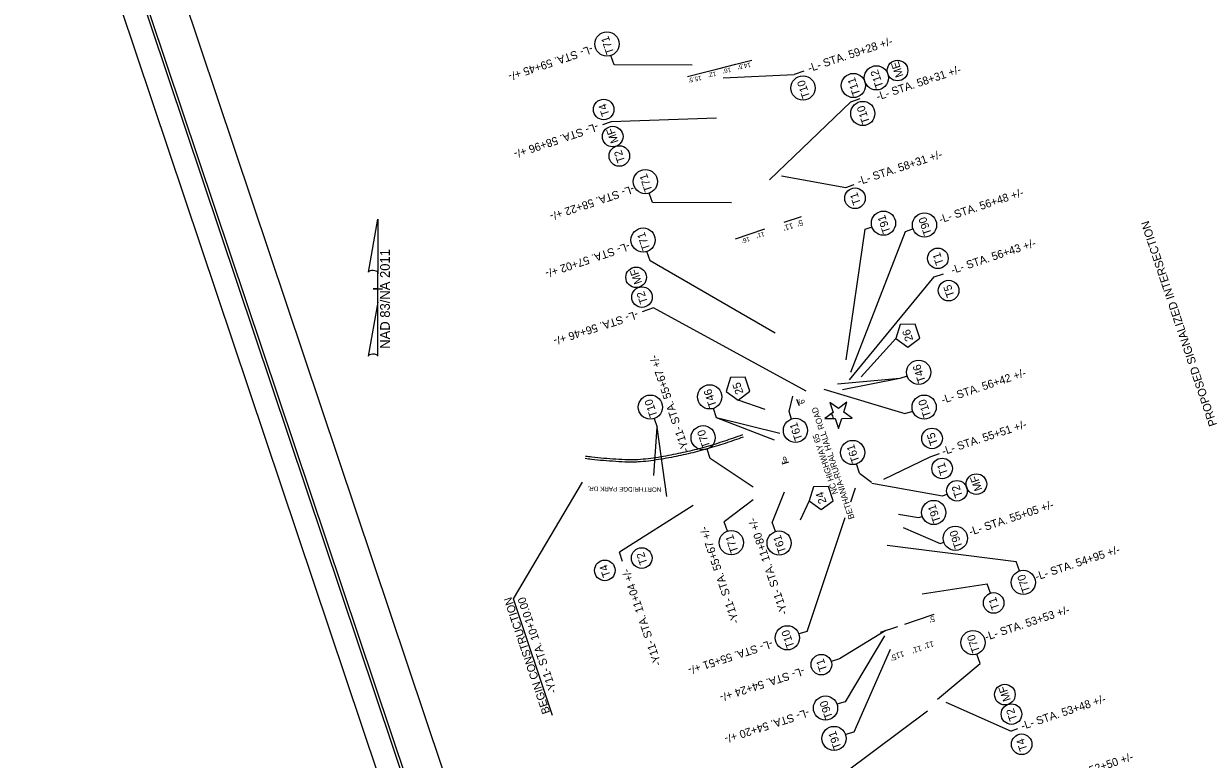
# Model space of a CAD drawing. Extents: x 1615436 to 1617119, y 903110 to 905145.
# Drawn here: x 1615436 to 1616462, y 903795 to 904439 of the extents above; entities that cross this region are included whole.
import ezdxf

# ---------------------------------------------------------------- set-up
doc = ezdxf.new("R2010")
doc.units = 0
for name, color, linetype in [('Default', 7, 'Continuous'), ('Prop Conc 2ft 6in Curb and Gutter', 7, 'Continuous'), ('Prop EOT', 7, 'Continuous'), ('Prop Horizontal Alignment Curve and Spiral Data', 7, 'Continuous'), ('Prop Horizontal Alignment Station Label', 7, 'Continuous'), ('Prop North Arrow NAD83 for Plan Sheets CELL', 7, 'Continuous'), ('Sheet Layout Plan Border', 7, 'Continuous'), ('Sheet Plan CELL', 7, 'Continuous'), ('Sheet Plot Border Inside CELL', 7, 'Continuous'), ('Sheet Plot Border Outside CELL', 7, 'Continuous'), ('Text', 7, 'Continuous')]:
    doc.layers.add(name, color=color, linetype=linetype)

msp = doc.modelspace()

# ---------------------------------------------------------------- linework, layer by layer
at = {"layer": 'Default'}
for p, q in [((1616143.4, 904097.7), (1616138.1, 904093.8)), ((1616138.1, 904093.8), (1616138.3, 904093.3)), ((1616138.3, 904093.3), (1616138.1, 904093.8)), ((1616138.3, 904093.3), (1616145.1, 904093.4))]:
    msp.add_line(p, q, dxfattribs=at)
for points in [[(1616144.9, 904098.8), (1616137.5, 904093.3), (1616146.7, 904093.4), (1616149.6, 904084.7), (1616152.4, 904093.5), (1616161.6, 904093.6), (1616154.1, 904098.9), (1616156.8, 904107.7), (1616149.5, 904102.2), (1616142, 904107.5), (1616144.9, 904098.8)], [(1616145.1, 904093.4), (1616146.7, 904093.4), (1616149.6, 904084.7), (1616152.4, 904093.5), (1616161.6, 904093.6), (1616154.1, 904098.9), (1616156.8, 904107.7), (1616149.5, 904102.2), (1616142, 904107.5), (1616144.9, 904098.8), (1616143.4, 904097.7)], [(1616138.1, 904093.8), (1616137.5, 904093.3), (1616138.3, 904093.3)]]:
    msp.add_lwpolyline(points, dxfattribs=at)
msp.add_ellipse((1616138.3, 904093.1), major_axis=(-0.95, 6.77), ratio=0.999591, start_param=4.623228, end_param=5.312334, dxfattribs=at)
msp.add_ellipse((1616138.3, 904093.1), major_axis=(-0.95, 6.77), ratio=0.999591, start_param=4.623228, end_param=5.312334, dxfattribs=at)
at = {"layer": 'Prop Conc 2ft 6in Curb and Gutter'}
msp.add_spline([(1616065.5, 904079.1), (1616049.8, 904073.6), (1616033.8, 904068.7), (1616025.7, 904066.4), (1616017.5, 904064.5), (1616009.2, 904062.7), (1616000.8, 904061), (1615991.9, 904059.4), (1615983, 904058.2), (1615974.1, 904057.4), (1615969.6, 904057.3), (1615965.2, 904057.3), (1615954.7, 904057.8), (1615944.1, 904058.5), (1615933.6, 904059.6), (1615928.3, 904060.2)], degree=3, dxfattribs=at)
at = {"layer": 'Prop EOT'}
msp.add_spline([(1616066.2, 904077.2), (1616050.4, 904071.7), (1616034.4, 904066.8), (1616026.2, 904064.5), (1616017.9, 904062.5), (1616009.6, 904060.7), (1616001.2, 904059), (1615992.2, 904057.5), (1615983.2, 904056.2), (1615974.2, 904055.4), (1615969.7, 904055.3), (1615965.2, 904055.3), (1615954.6, 904055.8), (1615944, 904056.6), (1615933.4, 904057.6), (1615928, 904058.3)], degree=3, dxfattribs=at)
at = {"layer": 'Prop Horizontal Alignment Curve and Spiral Data'}
msp.add_line((1615865.1, 903935.7), (1615925.7, 904037.8), dxfattribs=at)
at = {"layer": 'Prop Horizontal Alignment Station Label'}
msp.add_line((1615899.3, 903833.6), (1615865.1, 903935.7), dxfattribs=at)
at = {"layer": 'Prop North Arrow NAD83 for Plan Sheets CELL'}
for p, q in [((1615738.2, 904221.4), (1615746.4, 904267.8)), ((1615746.4, 904267.8), (1615746.4, 904267.8)), ((1615746.4, 904267.8), (1615746.4, 904267.8)), ((1615746.4, 904267.8), (1615746.4, 904220)), ((1615746.4, 904195.2), (1615746.4, 904221.4)), ((1615746.4, 904220), (1615746.4, 904221.3)), ((1615746, 904206.8), (1615742.4, 904206.8)), ((1615742.4, 904206.8), (1615742.4, 904206.8)), ((1615742.5, 904206.8), (1615750.5, 904206.8)), ((1615746.4, 904195.2), (1615738.1, 904147.9)), ((1615746.5, 904148.1), (1615746.4, 904195.2))]:
    msp.add_line(p, q, dxfattribs=at)
for centre, start_param, end_param in [((1615742.3, 904221), 0.216388, 2.908219), ((1615742.3, 904147.8), 0.201328, 3.141593)]:
    msp.add_ellipse(centre, major_axis=(4.23, -0.03), ratio=0.461098, start_param=start_param, end_param=end_param, dxfattribs=at)
at = {"layer": 'Sheet Layout Plan Border'}
msp.add_lwpolyline([(1616672.6, 903656.2), (1616919.8, 903656.8), (1616590.6, 904611.2), (1616386.8, 904624.4), (1616334.8, 904821.6), (1616466, 905009.6), (1615641.1, 904732.9), (1615700, 904557.2), (1615560.3, 904510.3), (1615954.2, 903336.2)], close=True, dxfattribs=at)
at = {"layer": 'Sheet Plan CELL'}
msp.add_lwpolyline([(1615463.1, 904697.6), (1615940.2, 903275.5), (1616935.7, 903609.4), (1616458.6, 905031.5)], close=True, dxfattribs=at)
at = {"layer": 'Sheet Plot Border Inside CELL'}
msp.add_lwpolyline([(1616986.9, 903464.7), (1616457, 905044.2), (1615456.8, 904708.7), (1615986.6, 903129.2)], close=True, dxfattribs=at)
at = {"layer": 'Sheet Plot Border Outside CELL'}
msp.add_lwpolyline([(1617010, 903458.7), (1616474.6, 905054.8), (1615436.4, 904706.6), (1615971.8, 903110.5)], close=True, dxfattribs=at)
at = {"layer": 'Text'}
for p, q in [((1615953.2, 904402.9), (1615950.4, 904411.2)), ((1616021.5, 904402.7), (1615953.2, 904402.9)), ((1616044, 904399.5), (1616059.6, 904403.6)), ((1616059.6, 904403.6), (1616073.6, 904407.2)), ((1616017.4, 904392.7), (1616032.3, 904396.5)), ((1616032.3, 904396.5), (1616044, 904399.5)), ((1616048.6, 904391.5), (1616110.9, 904394.6)), ((1616119.1, 904397.3), (1616110.9, 904394.6)), ((1616160.3, 904370.6), (1616168.5, 904373.4)), ((1616089.3, 904302.2), (1616160.3, 904370.6)), ((1615950.7, 904353), (1615943.2, 904350.4)), ((1616042.9, 904356.3), (1615950.7, 904353)), ((1616099.7, 904305.7), (1616155.9, 904295.7)), ((1615986.8, 904282.5), (1615984, 904290.8)), ((1616155.9, 904295.7), (1616163.4, 904298.2)), ((1616056, 904282.3), (1615986.8, 904282.5)), ((1616116.9, 904270), (1616101.7, 904264.9)), ((1616072.3, 904255.1), (1616085.1, 904259.4)), ((1616156.2, 904144.9), (1616172.9, 904259.1)), ((1616172.9, 904259.1), (1616178.9, 904261.1)), ((1616208.2, 904257.1), (1616214.7, 904259.4)), ((1616059.5, 904250.8), (1616072.3, 904255.1)), ((1616160.4, 904134), (1616208.2, 904257.1)), ((1615984.7, 904231.3), (1615982, 904239.5)), ((1616094.1, 904168.1), (1615984.7, 904231.3)), ((1616233.3, 904217.4), (1616241.5, 904220.1)), ((1616159.3, 904127.4), (1616233.3, 904217.4)), ((1615987.7, 904190.2), (1615977.9, 904186.9)), ((1616121.4, 904117.4), (1615987.7, 904190.2)), ((1616199.8, 904163.5), (1616169.3, 904129.9)), ((1616203.3, 904128.4), (1616148.7, 904123.4)), ((1616203.3, 904128.4), (1616153, 904118.6)), ((1616209.7, 904130.5), (1616203.3, 904128.4)), ((1616136.8, 904119.1), (1616207.7, 904097.8)), ((1616085.5, 904101.2), (1616061.8, 904109.6)), ((1616106.3, 904099.6), (1616109.6, 904113)), ((1616115.5, 904104.5), (1616113.1, 904110)), ((1616042.9, 904094.1), (1616040.2, 904102.3)), ((1616108.5, 904093), (1616106.3, 904099.6)), ((1616207.7, 904097.8), (1616214.5, 904100)), ((1615988, 904043.6), (1615990.9, 904085.9)), ((1615988.4, 904093.4), (1615990.9, 904085.9)), ((1615999.4, 904025.1), (1615990.9, 904085.9)), ((1616098.3, 904080.3), (1616042.9, 904094.1)), ((1616093.7, 904074.5), (1616042.9, 904094.1)), ((1616037.3, 904058.4), (1616034.5, 904066.6)), ((1616074.9, 904033.2), (1616037.3, 904058.4)), ((1616105.7, 904055.2), (1616099.9, 904053.5)), ((1616168, 904045.5), (1616165.2, 904053.7)), ((1616189.2, 904040.4), (1616229.9, 904060)), ((1616229.9, 904060), (1616238, 904062.8)), ((1616168, 904045.5), (1616178.5, 904037.6)), ((1616178.8, 904036.9), (1616240.5, 904025.9)), ((1616101.9, 904029), (1616091.5, 904002.7)), ((1616160.2, 904020.6), (1616164.3, 904032.8)), ((1616240.5, 904025.9), (1616244.6, 904027.3)), ((1616022.3, 904017.3), (1615957.9, 903976.5)), ((1616074.8, 904022.2), (1616049.6, 904003)), ((1616123.9, 904021.3), (1616115.9, 904004.4)), ((1616052.4, 903994.8), (1616049.6, 904003)), ((1616094.3, 903994.4), (1616091.5, 904002.7)), ((1616122.1, 903907.1), (1616155.5, 904006.7)), ((1616202, 904009.8), (1616219.5, 904006.7)), ((1616219.5, 904006.7), (1616222.8, 904007.8)), ((1616206, 903998.1), (1616238.5, 903984.1)), ((1616192.1, 903982.5), (1616305.1, 903968.3)), ((1616238.5, 903984.1), (1616241.8, 903985.3)), ((1615960.6, 903968.2), (1615957.9, 903976.5)), ((1616307.8, 903960.1), (1616305.1, 903968.3)), ((1616222.8, 903939.9), (1616279.7, 903948.7)), ((1616282.5, 903940.5), (1616279.7, 903948.7)), ((1616218.7, 903917.3), (1616233.2, 903922.1)), ((1616186.2, 903906.4), (1616201.4, 903911.5)), ((1616207.6, 903913.5), (1616218.7, 903917.3)), ((1616122.1, 903907.1), (1616114.9, 903904.9)), ((1616191, 903908), (1616150.3, 903883.1)), ((1616189.8, 903903.3), (1616155.4, 903845.6)), ((1616194.8, 903891.3), (1616163, 903819)), ((1616150.3, 903883.1), (1616143.1, 903880.8)), ((1616273.4, 903879.1), (1616270.6, 903887.3)), ((1616236.2, 903847.9), (1616273.4, 903879.1)), ((1616155.4, 903845.6), (1616148.2, 903843.4)), ((1616243.6, 903845.2), (1616300.7, 903819.8)), ((1616227.4, 903837.2), (1616156.1, 903784)), ((1616163, 903819), (1616155.8, 903816.8)), ((1616306.2, 903821.7), (1616300.7, 903819.8))]:
    msp.add_line(p, q, dxfattribs=at)
for points in [[(1616199.8, 904163.5), (1616210.3, 904156), (1616220.7, 904163.7), (1616216.5, 904176), (1616203.6, 904175.8)], [(1616051.3, 904117.1), (1616061.8, 904109.6), (1616072.1, 904117.4), (1616068, 904129.6), (1616055.1, 904129.4)], [(1616123.9, 904021.3), (1616134.5, 904013.8), (1616144.8, 904021.5), (1616140.7, 904033.8), (1616127.7, 904033.6)]]:
    msp.add_lwpolyline(points, close=True, dxfattribs=at)
for centre, radius in [((1615947, 904421.2), 10.6), ((1616201.2, 904398), 9.01), ((1616118.5, 904382.7), 10.6), ((1616162.6, 904384.9), 10.6), ((1616182.7, 904391.6), 10.6), ((1615944.1, 904363.9), 9.01), ((1616170.8, 904360.4), 10.6), ((1615952, 904340.2), 9.01), ((1615957.8, 904323.2), 9.01), ((1615980.6, 904300.8), 10.6), ((1616164, 904286.2), 9.01), ((1616188.9, 904264.4), 10.6), ((1616224.8, 904262.8), 10.6), ((1615978.6, 904249.6), 10.6), ((1616236.5, 904233.6), 9.01), ((1615972.5, 904217), 9.01), ((1615977.6, 904199.7), 9.01), ((1616245.9, 904205.4), 9.01), ((1616219.7, 904133.9), 10.6), ((1616036.8, 904112.4), 10.6), ((1615985, 904103.4), 10.6), ((1616224.5, 904103.4), 10.6), ((1616031.1, 904076.6), 10.6), ((1616111.9, 904083), 10.6), ((1616231.4, 904076), 9.01), ((1616161.9, 904063.7), 10.6), ((1616240.2, 904049.7), 9.01), ((1616270.2, 904036), 9.01), ((1616253.2, 904030.2), 9.01), ((1616232.9, 904011.2), 10.6), ((1616055.8, 903984.8), 10.6), ((1616097.6, 903984.4), 10.6), ((1616251.8, 903988.6), 10.6), ((1615977.4, 903971.3), 9.01), ((1615945.1, 903960.5), 9.01), ((1616311.2, 903950), 10.6), ((1616285.3, 903932), 9.01), ((1616104.8, 903901.5), 10.6), ((1616267.2, 903897.3), 10.6), ((1616134.6, 903878), 9.01), ((1616295.1, 903851.8), 9.01), ((1616138.2, 903840), 10.6), ((1616300.9, 903834.7), 9.01), ((1616145.7, 903813.4), 10.6), ((1616309.8, 903808.3), 9.01)]:
    msp.add_circle(centre, radius, dxfattribs=at)

# ---------------------------------------------------------------- texts
at = {"layer": 'Default'}
for s, height, rotation, p in [('PROPOSED SIGNALIZED INTERSECTION', 7.199, 108.5432, (1616480.9, 904088)), ('BETHANIA-RURAL HALL ROAD ', 5.25, 108.5432, (1616163.6, 904006.3)), ('NC HIGHWAY 65', 5.25, 108.5432, (1616149.3, 904028)), ('NORTHRIDGE PARK DR.', 4, 179.239, (1615994.6, 904033.1))]:
    msp.add_text(s, height=height, rotation=rotation, dxfattribs=at).set_placement(p)
at = {"layer": 'Prop Horizontal Alignment Station Label'}
for s, p in [('BEGIN CONSTRUCTION', (1615897.3, 903836.2)), ('-Y11- STA. 10+10.00 ', (1615903.3, 903854.2))]:
    msp.add_text(s, height=7, rotation=108.5432, dxfattribs=at).set_placement(p)
at = {"layer": 'Prop North Arrow NAD83 for Plan Sheets CELL'}
msp.add_text('NAD 83/NA 2011', height=8.5, rotation=90, dxfattribs=at).set_placement((1615757, 904154.5))
at = {"layer": 'Text'}
for s, height, rotation, p in [('T71', 7, 108.5432, (1615953.3, 904413.5)), ('-L- STA. 59+28 +/-', 7, 18.3607, (1616124, 904396.5)), ('-L- STA. 59+45 +/-', 7, 198.5432, (1615933.4, 904420.2)), ("14.5'", 3.93, 191.4623, (1616072.4, 904405)), ('ME', 7, 109.1388, (1616206.5, 904393.4)), ("15.5'", 3.93, 191.4623, (1616029.3, 904393.5)), ("12'", 3.93, 191.4623, (1616042.1, 904397.1)), ("16'", 3.93, 191.4623, (1616055.1, 904400.6)), ('T11', 7, 108.5432, (1616168.9, 904377.3)), ('T12', 7, 108.5432, (1616189, 904384)), ('-L- STA. 58+31 +/-', 7, 18.3607, (1616183.9, 904371.7)), ('T10', 7, 108.5432, (1616124.8, 904375)), ('T4', 7, 108.5124, (1615949.4, 904359.3)), ('T10', 7, 108.5432, (1616177.1, 904352.7)), ('-L- STA. 58+96 +/-', 7, 198.5432, (1615938.2, 904352.3)), ('MF', 7, 109.1388, (1615957.2, 904335.7)), ('T2', 7, 108.5124, (1615963, 904318.6)), ('-L- STA. 58+31 +/-', 7, 18.3607, (1616167.4, 904297.5)), ('T71', 7, 108.5432, (1615986.9, 904293.1)), ('-L- STA. 58+22 +/-', 7, 198.5432, (1615969.7, 904297.8)), ('T1', 7, 108.5124, (1616169.3, 904281.6)), ('-L- STA. 56+48 +/-', 7, 18.3607, (1616238.7, 904264.1)), ('T91', 7, 108.5432, (1616195.2, 904256.8)), ('T90', 7, 108.5432, (1616231.1, 904255.2)), ("11'", 5, 195.4638, (1616109.2, 904264.6)), ("5'", 5, 195.4638, (1616117.7, 904267.5)), ('T71', 7, 108.5432, (1615984.9, 904241.9)), ("16'", 3.93, 195.4638, (1616071.4, 904252.5)), ("11'", 3.93, 195.4638, (1616084.2, 904256.8)), ('-L- STA. 56+43 +/-', 7, 18.3607, (1616249.3, 904219.8)), ('-L- STA. 57+02 +/-', 7, 198.5432, (1615965.7, 904247.7)), ('T1', 7, 108.5124, (1616241.7, 904229)), ('MF', 7, 109.1388, (1615977.8, 904212.4)), ('T5', 7, 108.5124, (1616251.2, 904200.8)), ('T2', 7, 108.5124, (1615982.8, 904195.1)), ('-L- STA. 56+46 +/-', 7, 197.8667, (1615973.2, 904187.9)), ('26', 7, 108.5124, (1616215, 904162.3)), ('-Y11- STA. 55+67 +/-', 7, 108.5432, (1616019.1, 904065.5)), ('T46', 7, 108.5432, (1616226, 904126.2)), ('-L- STA. 56+42 +/-', 7, 18.3607, (1616240.8, 904106.2)), ('T46', 7, 108.5432, (1616043.1, 904104.7)), ('25', 7, 108.5124, (1616066.5, 904115.9)), ('T10', 7, 108.5432, (1615991.3, 904095.8)), ("6'", 5, 111.6622, (1616120.6, 904107.1)), ('T10', 7, 108.5432, (1616230.8, 904095.7)), ('T61', 7, 108.5432, (1616118.2, 904075.4)), ('-L- STA. 55+51 +/-', 7, 18.3607, (1616241.3, 904061.2)), ('T70', 7, 108.5432, (1616037.4, 904069)), ('T5', 7, 108.5124, (1616236.7, 904071.4)), ('T61', 7, 108.5432, (1616168.1, 904056.1)), ("6'", 5, 194.8297, (1616103.8, 904060.5)), ('T1', 7, 108.5124, (1616245.5, 904045.1)), ('T2', 7, 108.5124, (1616258.4, 904025.5)), ('MF', 7, 109.1388, (1616275.5, 904031.4)), ('24', 7, 108.5124, (1616139.2, 904020.1)), ('T91', 7, 108.5432, (1616239.2, 904003.6)), ('-L- STA. 55+05 +/-', 7, 18.3607, (1616265, 903990.8)), ('-Y11- STA. 11+80 +/-', 7, 108.5432, (1616105.3, 903923)), ('-Y11- STA. 55+67 +/-', 7, 108.5432, (1616062.9, 903915.3)), ('T90', 7, 108.5432, (1616258.1, 903981)), ('T71', 7, 108.5432, (1616062.1, 903977.1)), ('T61', 7, 108.5432, (1616103.9, 903976.8)), ('-L- STA. 54+95 +/-', 7, 18.3607, (1616322.9, 903951.6)), ('T2', 7, 108.5124, (1615982.6, 903966.7)), ('T4', 7, 108.5124, (1615950.3, 903955.8)), ('-Y11- STA. 11+04 +/-', 7, 108.5432, (1615994.8, 903878.3)), ('T70', 7, 108.5432, (1616317.5, 903942.4)), ('T1', 7, 108.5124, (1616290.6, 903927.3)), ("5'", 5, 195.4638, (1616233, 903920.8)), ('-L- STA. 53+53 +/-', 7, 18.3607, (1616278.9, 903898.9)), ('T10', 7, 108.5432, (1616111.1, 903893.8)), ('T70', 7, 108.5432, (1616273.5, 903889.7)), ('-L- STA. 55+51 +/-', 7, 197.8667, (1616090.9, 903899.8)), ("11'", 5, 195.4638, (1616206.3, 903890)), ("11'", 5, 195.4638, (1616221.7, 903894.9)), ("11'", 5, 195.4638, (1616232.2, 903898.8)), ('T1', 7, 108.5124, (1616139.8, 903873.4)), ("5'", 5, 195.4638, (1616199.4, 903887.3)), ('-L- STA. 54+24 +/-', 7, 197.8667, (1616118.7, 903875.9)), ('MF', 7, 109.1388, (1616300.4, 903847.2)), ('-L- STA. 53+48 +/-', 7, 18.3607, (1616310.5, 903820.8)), ('-L- STA. 54+20 +/-', 7, 197.8667, (1616122.8, 903839.5)), ('T90', 7, 109.1388, (1616144.7, 903832)), ('T2', 7, 108.5124, (1616306.1, 903830.1)), ('T91', 7, 109.1388, (1616152.2, 903805.4)), ('T4', 7, 108.5124, (1616315, 903803.7)), ('-L- STA. 52+50 +/-', 7, 18.3607, (1616334.6, 903770.2))]:
    msp.add_text(s, height=height, rotation=rotation, dxfattribs=at).set_placement(p)

doc.saveas('drawing.dxf')
